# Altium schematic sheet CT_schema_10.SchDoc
size 146 x 119 mm
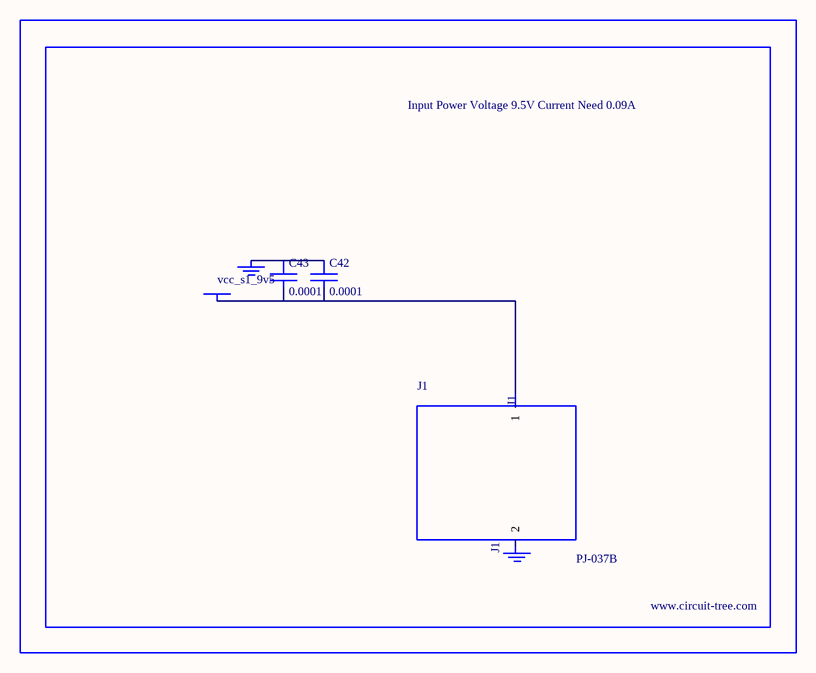
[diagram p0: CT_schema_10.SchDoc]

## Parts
BORDER9  (no value)
C42  0.0001  [EXV-9H]
C43  0.0001  [EXV-9H]
GND_INSTANCE_9_0  (no value)
GND_INSTANCE_9_1  (no value)
J1  PJ-037B  [PJ-037B_PACKAGE]
POWER_INSTANCE_9_0  vcc_s1_9v5

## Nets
NetC42_1: C42.1 C43.1 GND_INSTANCE_9_0.0(GND)
NetC42_2: C42.2 C43.2 J1.1 POWER_INSTANCE_9_0.0(PWR)

Not connected (* = marked no-connect by the designer): GND_INSTANCE_9_1 0(GND); J1 2

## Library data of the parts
BORDER9 = BORDER_PAGE9
C42 C43 = EDK107M035A9HAA
GND_INSTANCE_9_0 GND_INSTANCE_9_1 = GND
POWER_INSTANCE_9_0 = PWR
